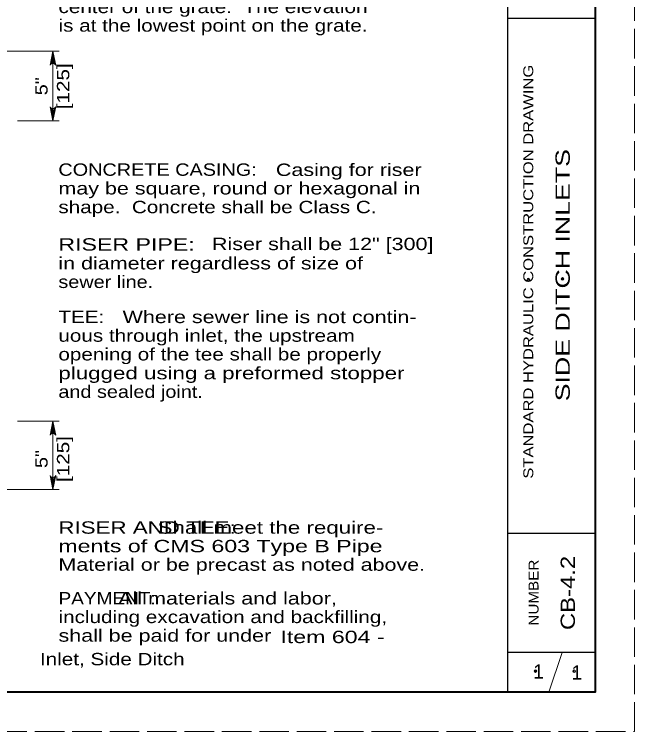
# Model space of a CAD drawing. Extents: x 1036.7 to 1070.7, y 883.9 to 905.9.
# Drawn here: x 1062.85 to 1070.67, y 883.91 to 892.96 of the extents above; entities that cross this region are included whole.
import ezdxf
from ezdxf.enums import TextEntityAlignment as Align

# ---------------------------------------------------------------- set-up
doc = ezdxf.new("R2010")
doc.units = 0
doc.header["$LTSCALE"] = 0.062
doc.header["$PDMODE"] = 32
doc.header["$PDSIZE"] = 0.031
doc.linetypes.add('LONG_DASHED', pattern=[7.5, 6, -1.5])
doc.layers.add('1', color=7, linetype='Continuous', lineweight=13)

msp = doc.modelspace()

# ---------------------------------------------------------------- linework, layer by layer
at = {"layer": '1', "lineweight": 25}
for p, q in [((1069.07333, 884.40825), (1069.07333, 905.40825)), ((1070.17333, 905.40825), (1070.17333, 884.40825)), ((1070.17333, 892.90825), (1069.07333, 892.90825)), ((1070.17333, 886.40825), (1069.07333, 886.40825)), ((1070.17333, 884.90825), (1069.07333, 884.90825))]:
    msp.add_line(p, q, dxfattribs=at)
at = {"layer": '1'}
for p, q in [((1062.55783, 892.494), (1063.41092, 892.494)), ((1063.30808, 892.33183), (1063.33283, 892.494)), ((1063.31842, 892.338), (1063.33283, 892.494)), ((1063.33283, 892.494), (1063.33283, 891.90817)), ((1063.33283, 892.34083), (1063.33283, 892.494)), ((1063.34417, 892.33917), (1063.33283, 892.494)), ((1063.35525, 892.33375), (1063.33283, 892.494)), ((1063.33283, 891.61667), (1063.33283, 891.90817)), ((1063.31042, 891.77692), (1063.33283, 891.61667)), ((1063.3215, 891.7715), (1063.33283, 891.61667)), ((1063.35758, 891.77883), (1063.33283, 891.61667)), ((1063.34725, 891.77267), (1063.33283, 891.61667)), ((1063.33283, 891.76983), (1063.33283, 891.61667)), ((1062.88475, 891.61667), (1063.41092, 891.61667)), ((1062.88475, 887.82533), (1063.41092, 887.82533)), ((1063.30808, 887.66325), (1063.33283, 887.82533)), ((1063.31842, 887.66933), (1063.33283, 887.82533)), ((1063.33283, 887.82533), (1063.33283, 887.23758)), ((1063.33283, 887.67217), (1063.33283, 887.82533)), ((1063.34417, 887.6705), (1063.33283, 887.82533)), ((1063.35525, 887.66508), (1063.33283, 887.82533)), ((1063.33283, 886.96275), (1063.33283, 887.23758)), ((1063.31042, 887.123), (1063.33283, 886.96275)), ((1063.3215, 887.11758), (1063.33283, 886.96275)), ((1063.35758, 887.12492), (1063.33283, 886.96275)), ((1063.34725, 887.11875), (1063.33283, 886.96275)), ((1063.33283, 887.11592), (1063.33283, 886.96275)), ((1062.55783, 886.96275), (1063.41092, 886.96275)), ((1069.59, 884.40825), (1069.75667, 884.90825))]:
    msp.add_line(p, q, dxfattribs=at)
at = {"layer": '1', "linetype": 'LONG_DASHED'}
msp.add_lwpolyline([(1036.67333, 883.90825), (1070.67333, 883.90825), (1070.67333, 905.90825), (1036.67333, 905.90825)], close=True, dxfattribs=at)
at = {"layer": '1', "lineweight": 25}
msp.add_lwpolyline([(1070.17333, 884.40825), (1038.67333, 884.40825), (1038.67333, 905.40825)], dxfattribs=at)
at = {"layer": '1', "lineweight": 40}
msp.add_lwpolyline([(1038.67333, 905.40825), (1070.17333, 905.40825), (1070.17333, 884.40825), (1038.67333, 884.40825)], close=True, dxfattribs=at)
msp.add_lwpolyline([(1038.67333, 905.40825), (1070.17333, 905.40825), (1070.17333, 884.40825), (1038.67333, 884.40825)], close=True, dxfattribs=at)
at = {"layer": '1'}
for points in [[(1063.29742, 892.317), (1063.33283, 892.494), (1063.36825, 892.317)], [(1063.36825, 891.79367), (1063.33283, 891.61667), (1063.29742, 891.79367)], [(1063.29742, 887.64833), (1063.33283, 887.82533), (1063.36825, 887.64833)], [(1063.36825, 887.13975), (1063.33283, 886.96275), (1063.29742, 887.13975)]]:
    msp.add_lwpolyline(points, dxfattribs=at)
for centre, start, end in [((1063.33286, 892.3027), 22.08782, 157.91395), ((1063.33278, 891.80796), 202.08782, 337.91395), ((1063.33286, 887.63406), 22.08782, 157.91395), ((1063.33278, 887.15406), 202.08782, 337.91395)]:
    msp.add_arc(centre, 0.0382, start, end, dxfattribs=at)
for p in [(1069.33075, 889.61425), (1069.76358, 889.62158), (1069.42142, 884.672), (1069.90983, 884.671)]:
    msp.add_point(p, dxfattribs=at)

# ---------------------------------------------------------------- texts
for s, width, p in [('center of the grate.  The elevation', 1.25, (1063.40325, 892.97533)), ('is at the lowest point on the grate.', 1.25, (1063.40325, 892.74133)), ('CONCRETE CASING:', 1.2, (1063.40133, 890.92258)), ('Casing for riser', 1.3, (1066.14617, 890.92058)), ('may be square, round or hexagonal in', 1.3, (1063.40133, 890.68658)), ('shape.  Concrete shall be Class C.', 1.25, (1063.40133, 890.45058)), ('RISER PIPE:', 1.4, (1063.40133, 889.97858)), ('Riser shall be 12" [300]', 1.3, (1065.33958, 889.98467)), ('in diameter regardless of size of', 1.3, (1063.40133, 889.74125)), ('sewer line.', 1.2, (1063.40133, 889.50658)), ('Where sewer line is not contin-', 1.3, (1064.21217, 889.06358)), ('TEE:', 1.25, (1063.40133, 889.06442)), ('uous through inlet, the upstream', 1.25, (1063.40133, 888.82842)), ('opening of the tee shall be properly', 1.25, (1063.40133, 888.59242)), ('plugged using a preformed stopper', 1.35, (1063.40133, 888.35508)), ('and sealed joint.', 1.2, (1063.40133, 888.12042)), ('RISER AND TEE:', 1.35, (1063.40133, 886.40617)), ('                Shall meet the require-', 1.35, (1063.40133, 886.40617)), ('ments of CMS 603 Type B Pipe', 1.4, (1063.40133, 886.17217)), ('Material or be precast as noted above.', 1.3, (1063.40133, 885.93817)), ('PAYMENT:', 1.15, (1063.40325, 885.51342)), ('          All materials and labor, ', 1.3, (1063.40325, 885.51283)), ('including excavation and backfilling, ', 1.25, (1063.40325, 885.27817)), ('shall be paid for under', 1.3, (1063.40325, 885.0435)), ('        Item 604 - ', 1.4, (1065.55392, 885.02575)), ('   Inlet, Side Ditch', 1.25, (1062.95125, 884.74567))]:
    msp.add_text(s, height=0.156, dxfattribs=dict(at, width=width)).set_placement(p)
for s, height, width, p in [('[125]', 0.156, 1.25, (1063.53917, 892.05233)), ('STANDARD HYDRAULIC CONSTRUCTION DRAWING', 0.125, 1.25, (1069.39325, 889.71229)), ('5"', 0.156, 1.2, (1063.26517, 892.05237)), ('SIDE DITCH INLETS', 0.18, 1.4, (1069.85492, 889.66846)), ('[125]', 0.156, 1.25, (1063.53917, 887.3485)), ('5"', 0.156, 1.2, (1063.26517, 887.34854)), ('NUMBER', 0.125, 1.15, (1069.46033, 885.66233)), ('CB-4.2', 0.18, 1.25, (1069.91967, 885.65858))]:
    msp.add_text(s, height=height, rotation=90, dxfattribs=dict(at, width=width)).set_placement(p, align=Align.CENTER)
for p in [(1069.46118, 884.57833), (1069.94402, 884.56575)]:
    msp.add_text('1', height=0.18, dxfattribs=at).set_placement(p, align=Align.CENTER)

doc.saveas('drawing.dxf')
